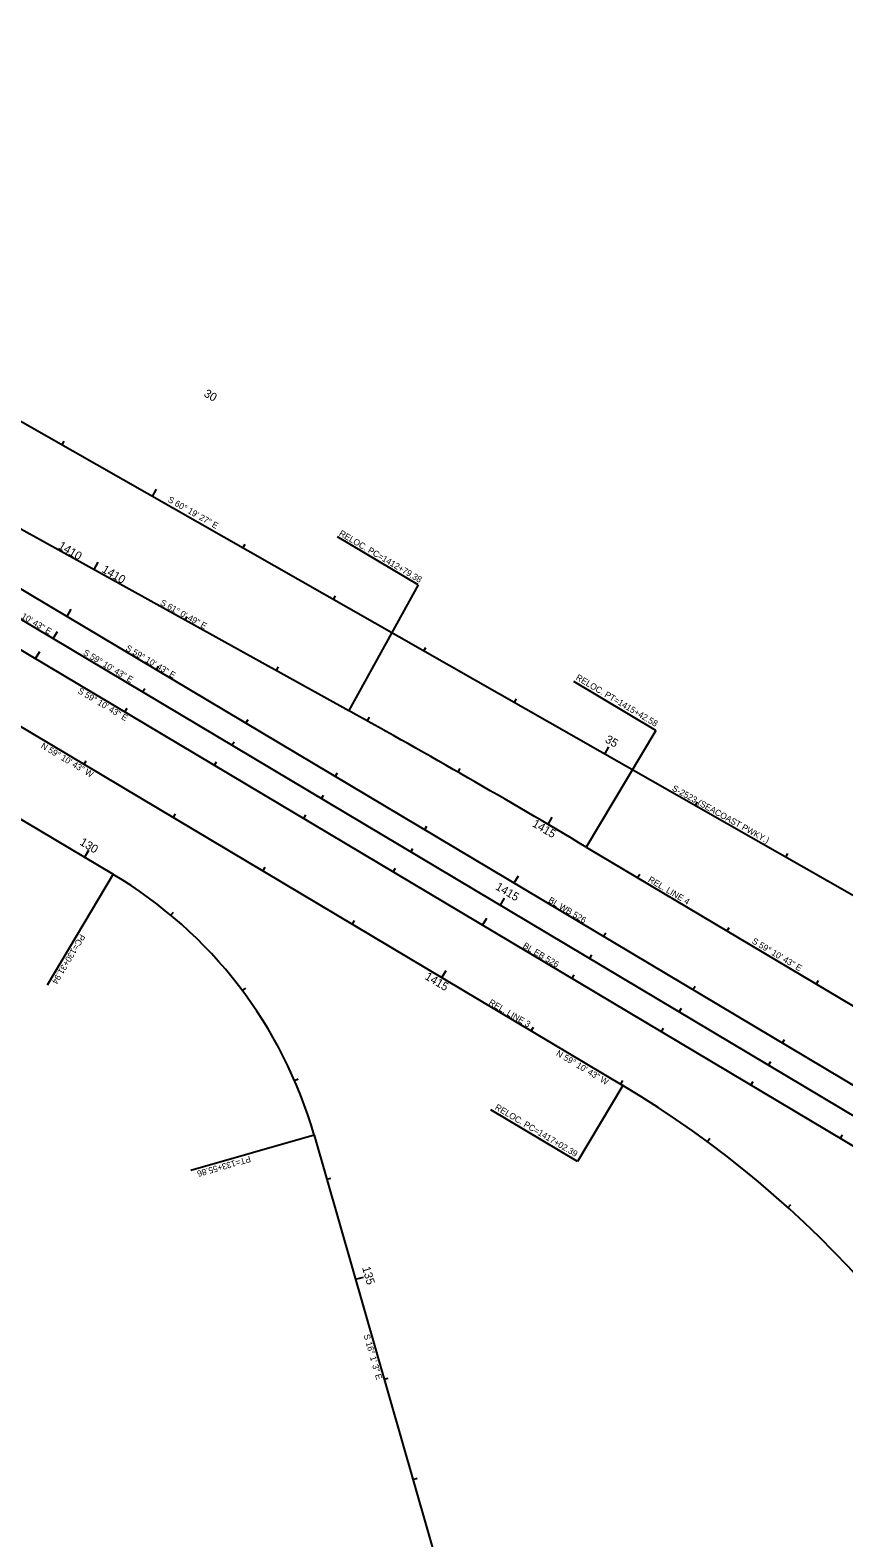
# Model space of a CAD drawing. Extents: x 2339194 to 2355375, y 360879 to 375175.
# Drawn here: x 2347367 to 2348148, y 368361 to 369810 of the extents above; entities that cross this region are included whole.
import ezdxf

# ---------------------------------------------------------------- set-up
doc = ezdxf.new("R2010")
doc.units = 0
for name, color, linetype in [('RD_HC_Cl', 7, 'Continuous'), ('RD_HC_CL_Rel', 7, 'Continuous'), ('RD_HC_Data', 7, 'Continuous'), ('RD_HC_Data_Rel', 7, 'Continuous'), ('RD_HC_Data_Tic', 7, 'Continuous'), ('RD_HC_Data_Tic_Rel', 7, 'Continuous'), ('RD_HC_TX_Rel_Sta50', 7, 'Continuous'), ('RD_HC_TX_Sta50', 7, 'Continuous')]:
    doc.layers.add(name, color=color, linetype=linetype)

msp = doc.modelspace()

# ---------------------------------------------------------------- linework, layer by layer
at = {"layer": 'RD_HC_Cl'}
for p, q in [((2346281.6, 369885.4), (2351112.4, 367003.2)), ((2347125.2, 369566.1), (2348362.6, 368861)), ((2347131.9, 369186), (2347446.2, 368998.5)), ((2347639.2, 368747.8), (2347994.6, 367509.7))]:
    msp.add_line(p, q, dxfattribs=at)
msp.add_arc((2347225.9, 368629.2), 430, 16.0174, 59.1785, dxfattribs=at)
at = {"layer": 'RD_HC_CL_Rel'}
for p, q in [((2346294.5, 369907), (2348311.8, 368703.5)), ((2346268.7, 369863.8), (2348286, 368660.2)), ((2346236.3, 369809.5), (2347935.6, 368795.6)), ((2346990.8, 369533.5), (2347672.4, 369155.9)), ((2347900.5, 369024.7), (2348345.9, 368759))]:
    msp.add_line(p, q, dxfattribs=at)
for centre, radius, start, end in [((2343690.2, 361967.9), 8217.3, 59.17851, 61.01367), ((2347423.3, 367936.8), 1000, 22.7108, 59.1785)]:
    msp.add_arc(centre, radius, start, end, dxfattribs=at)
at = {"layer": 'RD_HC_Data'}
for p, q in [((2347446.2, 368998.5), (2347382.7, 368892.1)), ((2347639.2, 368747.8), (2347520.7, 368713.8))]:
    msp.add_line(p, q, dxfattribs=at)
at = {"layer": 'RD_HC_Data_Rel'}
for p, q in [((2347739.2, 369276.6), (2347661.6, 369322.9)), ((2347739.2, 369276.6), (2347672.4, 369155.9)), ((2347967.3, 369136.7), (2347888.5, 369183.7)), ((2347967.3, 369136.7), (2347900.5, 369024.7)), ((2347935.6, 368795.6), (2347892, 368722.5)), ((2347892, 368722.5), (2347808.8, 368772.2))]:
    msp.add_line(p, q, dxfattribs=at)
at = {"layer": 'RD_HC_Data_Tic'}
for p, q in [((2347397.1, 369411.2), (2347399.1, 369414.6)), ((2347484, 369361.6), (2347487.9, 369368.6)), ((2347570.8, 369312.1), (2347572.8, 369315.6)), ((2347657.7, 369262.6), (2347659.7, 369266.1)), ((2347388.6, 369225), (2347392.7, 369231.8)), ((2347744.6, 369213.1), (2347746.6, 369216.6)), ((2347474.5, 369173.7), (2347476.5, 369177.2)), ((2347831.5, 369163.6), (2347833.5, 369167.1)), ((2347560.3, 369122.5), (2347562.4, 369125.9)), ((2347918.4, 369114.1), (2347922.3, 369121.1)), ((2347646.2, 369071.2), (2347648.3, 369074.7)), ((2348005.3, 369064.6), (2348007.2, 369068.1)), ((2347418.8, 369014.8), (2347422.9, 369021.7)), ((2347732.1, 369020), (2347734.1, 369023.4)), ((2348092.2, 369015.1), (2348094.1, 369018.6)), ((2347818, 368968.8), (2347822.1, 368975.6)), ((2347501.6, 368959.1), (2347504.2, 368962.2)), ((2347903.9, 368917.5), (2347905.9, 368921)), ((2347570.3, 368886.7), (2347573.5, 368889.1)), ((2347989.7, 368866.3), (2347991.8, 368869.7)), ((2348075.6, 368815.1), (2348077.7, 368818.5)), ((2347620.3, 368800.4), (2347624, 368802)), ((2347651.4, 368705.4), (2347655.2, 368706.5)), ((2347679, 368609.3), (2347686.6, 368611.5)), ((2347706.5, 368513.2), (2347710.4, 368514.3)), ((2347734.1, 368417), (2347738, 368418.2))]:
    msp.add_line(p, q, dxfattribs=at)
at = {"layer": 'RD_HC_Data_Tic_Rel'}
for p, q in [((2347428, 369291.3), (2347431.9, 369298.3)), ((2347401.9, 369246.3), (2347406, 369253.2)), ((2347515.4, 369242.9), (2347517.4, 369246.4)), ((2347371.6, 369205.8), (2347375.7, 369212.6)), ((2347487.7, 369195.1), (2347489.8, 369198.5)), ((2347602.9, 369194.4), (2347604.9, 369197.9)), ((2347457.5, 369154.5), (2347459.5, 369158)), ((2347573.6, 369143.9), (2347575.7, 369147.3)), ((2347690.4, 369145.9), (2347692.3, 369149.4)), ((2347418.3, 369104.3), (2347420.4, 369107.7)), ((2347543.4, 369103.3), (2347545.4, 369106.7)), ((2347659.5, 369092.6), (2347661.5, 369096.1)), ((2347777.4, 369096.7), (2347779.4, 369100.2)), ((2347504.2, 369053), (2347506.2, 369056.5)), ((2347629.2, 369052.1), (2347631.3, 369055.5)), ((2347745.4, 369041.4), (2347747.4, 369044.8)), ((2347863.9, 369046.4), (2347867.9, 369053.3)), ((2347590.1, 369001.8), (2347592.1, 369005.2)), ((2347715.1, 369000.8), (2347717.2, 369004.3)), ((2347831.2, 368990.2), (2347835.3, 368997)), ((2347949.8, 368995.3), (2347951.9, 368998.7)), ((2347676, 368950.5), (2347678, 368954)), ((2347801, 368949.6), (2347805.1, 368956.5)), ((2347917.1, 368938.9), (2347919.2, 368942.4)), ((2348035.7, 368944.1), (2348037.7, 368947.5)), ((2347761.8, 368899.3), (2347765.9, 368906.2)), ((2347886.9, 368898.4), (2347888.9, 368901.8)), ((2348003, 368887.7), (2348005.1, 368891.1)), ((2348121.6, 368892.8), (2348123.6, 368896.3)), ((2347847.7, 368848.1), (2347849.8, 368851.5)), ((2347972.8, 368847.1), (2347974.8, 368850.6)), ((2348088.9, 368836.4), (2348090.9, 368839.9)), ((2347933.6, 368796.8), (2347935.6, 368800.3)), ((2348058.6, 368795.9), (2348060.7, 368799.3)), ((2348016.9, 368741.6), (2348019.3, 368744.8)), ((2348144.5, 368744.6), (2348146.6, 368748.1)), ((2348094.3, 368678.3), (2348096.9, 368681.3))]:
    msp.add_line(p, q, dxfattribs=at)

# ---------------------------------------------------------------- texts
at = {"layer": 'RD_HC_Data'}
for s, rotation, p in [('S 60%%d 19\' 27" E', 330.3243, (2347498.1, 369356.9)), ('S-2523 (SEACOAST PWKY.)', 330.693, (2347982.3, 369079.4)), ('PC=130+31.94', 239.1785, (2347414.6, 368941.6)), ('PT=133+55.86', 196.0174, (2347577.3, 368728)), ('S 16%%d 1\' 3" E', 286.0174, (2347686.6, 368555.6))]:
    msp.add_text(s, height=6, rotation=rotation, dxfattribs=at).set_placement(p)
at = {"layer": 'RD_HC_Data_Rel'}
for s, rotation, p in [('RELOC. PC=1412+79.38', 329.4134, (2347662.5, 369324.5)), ('S 61%%d 0\' 49" E', 331.0137, (2347490.8, 369257.8)), ('S 59%%d 10\' 43" E', 329.1785, (2347338.6, 369256.3)), ('S 59%%d 10\' 43" E', 329.1785, (2347457.6, 369214.2)), ('S 59%%d 10\' 43" E', 329.1785, (2347416.8, 369209.9)), ('RELOC. PT=1415+42.58', 329.1785, (2347889.9, 369186)), ('S 59%%d 10\' 43" E', 329.1785, (2347411.6, 369173.1)), ('N 59%%d 10\' 43" W', 329.1785, (2347376.2, 369120.3)), ('REL. LINE 4', 329.1785, (2347959.3, 368991.8)), ('BL WB 526', 329.1056, (2347863.5, 368972)), ('BL EB 526', 329.1056, (2347839.1, 368928.3)), ('S 59%%d 10\' 43" E', 329.1785, (2348059, 368932.7)), ('REL. LINE 3', 329.5983, (2347806.3, 368873.7)), ('N 59%%d 10\' 43" W', 329.1785, (2347871, 368824.8)), ('RELOC. PC=1417+02.39', 329.1785, (2347812.2, 368773))]:
    msp.add_text(s, height=6, rotation=rotation, dxfattribs=at).set_placement(p)
at = {"layer": 'RD_HC_TX_Rel_Sta50'}
for s, rotation, p in [('1410', 329.1785, (2347392.7, 369312.1)), ('1410', 329.1785, (2347434.6, 369289.5)), ('1415', 329.4754, (2347847.9, 369045)), ('1415', 329.1785, (2347744.8, 368898.2))]:
    msp.add_text(s, height=8, rotation=rotation, dxfattribs=at).set_placement(p)
at = {"layer": 'RD_HC_TX_Sta50'}
for s, rotation, p in [('30', 330.3243, (2347532.6, 369458.3)), ('35', 330.3243, (2347917.9, 369125.9)), ('130', 329.1785, (2347413.4, 369027.4)), ('1415', 329.1785, (2347812.6, 368984.5)), ('135', 286.0174, (2347685.2, 368620.5))]:
    msp.add_text(s, height=8, rotation=rotation, dxfattribs=at).set_placement(p)

doc.saveas('drawing.dxf')
